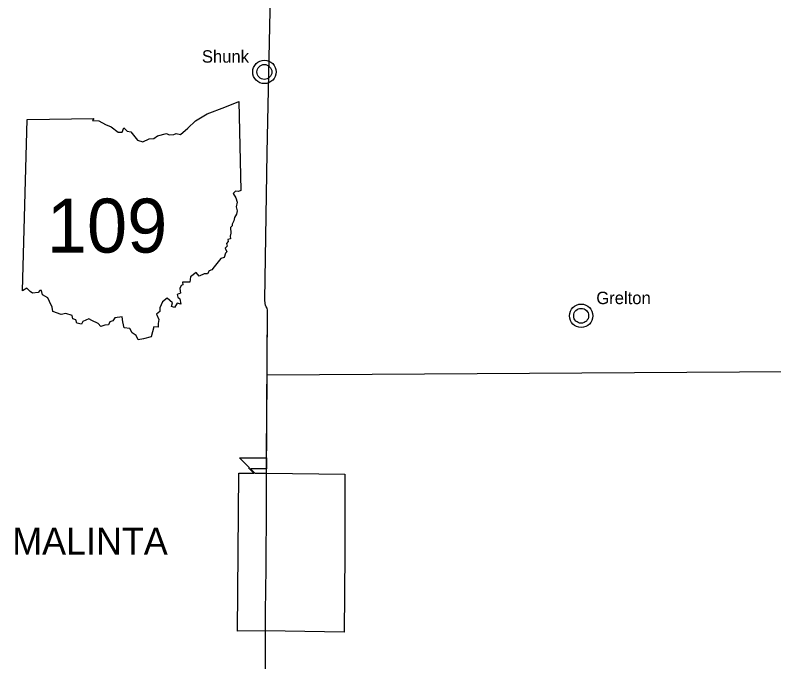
# Model space of a CAD drawing. Extents: x -62 to 810, y 0 to 440.
# Drawn here: x 335.6 to 408.1, y 199.3 to 261.1 of the extents above; entities that cross this region are included whole.
import ezdxf

# ---------------------------------------------------------------- set-up
doc = ezdxf.new("R2010")
doc.units = 0
for name, color, linetype in [('DV_X_Corp_Line', 7, 'Continuous'), ('GM_X_Corporation_Text', 7, 'Continuous'), ('GM_X_State_Route', 7, 'Continuous'), ('PV_P_Text', 7, 'Continuous'), ('SH_Data', 7, 'Continuous'), ('SH_Text', 7, 'Continuous')]:
    doc.layers.add(name, color=color, linetype=linetype)

msp = doc.modelspace()

# ---------------------------------------------------------------- linework, layer by layer
at = {"layer": 'DV_X_Corp_Line'}
msp.add_lwpolyline([(356.853, 202.268), (356.979, 217.337), (358.432, 217.338), (357.932, 217.847), (358.01, 217.847), (357.072, 218.808), (359.65, 218.81), (359.646, 217.756), (358.099, 217.756), (358.508, 217.338), (359.644, 217.339), (367.127, 217.24), (367.122, 209.65), (367.076, 202.159), (359.536, 202.269)], close=True, dxfattribs=at)
for centre, radius in [((359.439, 255.689), 1.12), ((359.439, 255.689), 0.71), ((389.717, 232.386), 1.12), ((389.717, 232.386), 0.71)]:
    msp.add_circle(centre, radius, dxfattribs=at)
at = {"layer": 'GM_X_State_Route'}
for points in [[(359.66, 220.968), (359.691, 227.727), (359.734, 232.912), (359.691, 233.115), (359.617, 233.258), (359.542, 233.389), (359.497, 233.555), (359.48, 233.903), (359.693, 247.954), (359.849, 255.51), (360.007, 263.095)], [(359.644, 217.339), (359.646, 217.941), (359.66, 220.968)], [(359.633, 213.907), (359.633, 213.976), (359.639, 215.824), (359.644, 217.339)], [(359.628, 212.713), (359.629, 212.757), (359.629, 212.774), (359.629, 212.789), (359.632, 213.716), (359.633, 213.907)], [(359.624, 211.519), (359.624, 211.575), (359.625, 211.9), (359.628, 212.713)], [(359.621, 210.773), (359.622, 211.146), (359.624, 211.519)], [(359.617, 209.729), (359.617, 209.775), (359.619, 210.209), (359.621, 210.773)], [(359.575, 205.85), (359.612, 208.591), (359.617, 209.684), (359.617, 209.729)], [(359.536, 202.269), (359.556, 204.456), (359.575, 205.85)], [(359.434, 171.906), (359.436, 180.111), (359.466, 181.196), (359.519, 182.504), (359.536, 182.647), (359.668, 182.933), (360.195, 184.201), (360.235, 184.32), (360.287, 184.749), (360.304, 187.082), (360.347, 192.838), (360.319, 192.998), (360.194, 193.261), (359.618, 194.444), (359.55, 194.638), (359.533, 195.169), (359.536, 202.269)]]:
    msp.add_lwpolyline(points, dxfattribs=at)
at = {"layer": 'PV_P_Text'}
msp.add_line((336.307, 234.774), (336.765, 251.147), dxfattribs=at)
msp.add_line((336.307, 234.774), (336.765, 251.147), dxfattribs=at)
for points in [[(336.765, 251.147), (343.118, 251.254), (343.019, 251.056), (343.618, 251.015), (344.255, 250.665), (344.793, 250.444), (345.452, 249.923), (345.846, 249.929), (346.013, 250.356), (346.315, 250.027), (346.673, 249.968), (347.292, 249.184), (347.804, 249.014), (348.416, 249.283), (348.874, 249.327), (349.208, 249.593), (350.08, 249.82), (350.323, 249.684), (350.784, 249.711), (351.017, 249.812), (351.419, 249.722), (352.128, 250.317), (352.857, 251.019), (353.979, 251.681), (355.655, 252.309), (356.98, 252.87), (357.172, 244.373)], [(336.765, 251.147), (343.118, 251.254), (343.019, 251.056), (343.618, 251.015), (344.255, 250.665), (344.793, 250.444), (345.452, 249.923), (345.846, 249.929), (346.013, 250.356), (346.315, 250.027), (346.673, 249.968), (347.292, 249.184), (347.804, 249.014), (348.416, 249.283), (348.874, 249.327), (349.208, 249.593), (350.08, 249.82), (350.323, 249.684), (350.784, 249.711), (351.017, 249.812), (351.419, 249.722), (352.128, 250.317), (352.857, 251.019), (353.979, 251.681), (355.655, 252.309), (356.98, 252.87), (357.172, 244.373)], [(357.172, 244.373), (356.976, 244.254), (356.672, 244.31), (356.467, 244.072), (356.72, 243.674), (356.84, 243.254), (356.734, 242.791), (356.839, 242.409), (356.767, 242.09), (356.576, 241.772), (356.51, 241.468), (356.348, 241.149), (356.361, 240.97), (356.206, 240.828), (356.234, 240.297), (356.156, 240.002), (356.182, 239.748), (355.931, 239.682), (355.989, 239.472), (355.829, 239.31), (355.863, 239.031), (355.681, 238.853), (355.858, 238.496), (355.716, 238.383), (355.599, 237.95), (355.276, 237.862), (354.63, 237.069), (354.402, 236.769), (354.146, 236.694), (354.005, 236.386), (353.689, 236.385), (353.212, 236.172), (352.904, 236.539), (352.363, 236.097), (352.301, 235.587), (351.617, 235.603), (351.644, 235.345), (351.492, 235.27), (351.353, 235.011), (351.433, 234.552), (351.114, 234.435), (351.152, 234.167), (351.357, 234.004), (351.448, 233.495), (351.108, 233.598), (350.829, 233.168), (350.543, 233.269), (350.637, 233.633), (350.153, 234.071), (349.695, 233.72), (349.456, 233.16), (349.454, 232.783), (349.112, 232.555), (349.331, 232.023), (349.291, 231.656), (349.298, 231.308), (348.871, 231.32), (348.613, 230.38)], [(357.172, 244.373), (356.976, 244.254), (356.672, 244.31), (356.467, 244.072), (356.72, 243.674), (356.84, 243.254), (356.734, 242.791), (356.839, 242.409), (356.767, 242.09), (356.576, 241.772), (356.51, 241.468), (356.348, 241.149), (356.361, 240.97), (356.206, 240.828), (356.234, 240.297), (356.156, 240.002), (356.182, 239.748), (355.931, 239.682), (355.989, 239.472), (355.829, 239.31), (355.863, 239.031), (355.681, 238.853), (355.858, 238.496), (355.716, 238.383), (355.599, 237.95), (355.276, 237.862), (354.63, 237.069), (354.402, 236.769), (354.146, 236.694), (354.005, 236.386), (353.689, 236.385), (353.212, 236.172), (352.904, 236.539), (352.363, 236.097), (352.301, 235.587), (351.617, 235.603), (351.644, 235.345), (351.492, 235.27), (351.353, 235.011), (351.433, 234.552), (351.114, 234.435), (351.152, 234.167), (351.357, 234.004), (351.448, 233.495), (351.108, 233.598), (350.829, 233.168), (350.543, 233.269), (350.637, 233.633), (350.153, 234.071), (349.695, 233.72), (349.456, 233.16), (349.454, 232.783), (349.112, 232.555), (349.331, 232.023), (349.291, 231.656), (349.298, 231.308), (348.871, 231.32), (348.613, 230.38)], [(348.613, 230.38), (347.872, 230.2), (347.357, 230.093), (347.176, 230.52), (346.808, 230.745), (346.568, 231.175), (346.04, 231.233), (345.914, 231.824), (345.855, 232.303), (345.133, 232.185), (344.935, 231.892), (344.678, 231.813), (344.529, 231.518), (344.18, 231.493), (343.805, 231.354), (343.56, 231.643), (342.946, 231.934), (342.67, 232.084), (342.092, 231.851), (341.969, 231.575), (341.51, 231.697), (341.402, 232.005), (341.124, 232.097), (341.062, 232.423), (340.468, 232.597), (340.013, 232.527), (339.211, 232.79), (339.163, 233.219), (338.889, 233.742), (338.747, 234.105), (338.24, 234.382), (338.137, 234.814), (337.975, 234.801), (337.827, 234.626), (337.264, 234.545), (337.039, 234.722), (336.724, 235.023), (336.307, 234.774)], [(348.613, 230.38), (347.872, 230.2), (347.357, 230.093), (347.176, 230.52), (346.808, 230.745), (346.568, 231.175), (346.04, 231.233), (345.914, 231.824), (345.855, 232.303), (345.133, 232.185), (344.935, 231.892), (344.678, 231.813), (344.529, 231.518), (344.18, 231.493), (343.805, 231.354), (343.56, 231.643), (342.946, 231.934), (342.67, 232.084), (342.092, 231.851), (341.969, 231.575), (341.51, 231.697), (341.402, 232.005), (341.124, 232.097), (341.062, 232.423), (340.468, 232.597), (340.013, 232.527), (339.211, 232.79), (339.163, 233.219), (338.889, 233.742), (338.747, 234.105), (338.24, 234.382), (338.137, 234.814), (337.975, 234.801), (337.827, 234.626), (337.264, 234.545), (337.039, 234.722), (336.724, 235.023), (336.307, 234.774)]]:
    msp.add_lwpolyline(points, dxfattribs=at)
at = {"layer": 'SH_Data'}
msp.add_line((487.742, 227.57), (359.697, 226.704), dxfattribs=at)
at = {"layer": 'SH_Text'}
for p, q in [((359.65, 218.81), (359.734, 232.912)), ((359.55, 194.638), (359.536, 202.269))]:
    msp.add_line(p, q, dxfattribs=at)

# ---------------------------------------------------------------- texts
at = {"layer": 'GM_X_Corporation_Text'}
for s, height, p in [('Shunk', 1.1875, (353.461, 256.576)), ('Grelton', 1.1875, (391.164, 233.503)), ('MALINTA', 2.565, (335.332, 209.576))]:
    msp.add_text(s, height=height, rotation=0.00001, dxfattribs=at).set_placement(p)
at = {"layer": 'PV_P_Text'}
msp.add_text('109', height=5.1621, dxfattribs=at).set_placement((338.638, 238.425))

doc.saveas('drawing.dxf')
